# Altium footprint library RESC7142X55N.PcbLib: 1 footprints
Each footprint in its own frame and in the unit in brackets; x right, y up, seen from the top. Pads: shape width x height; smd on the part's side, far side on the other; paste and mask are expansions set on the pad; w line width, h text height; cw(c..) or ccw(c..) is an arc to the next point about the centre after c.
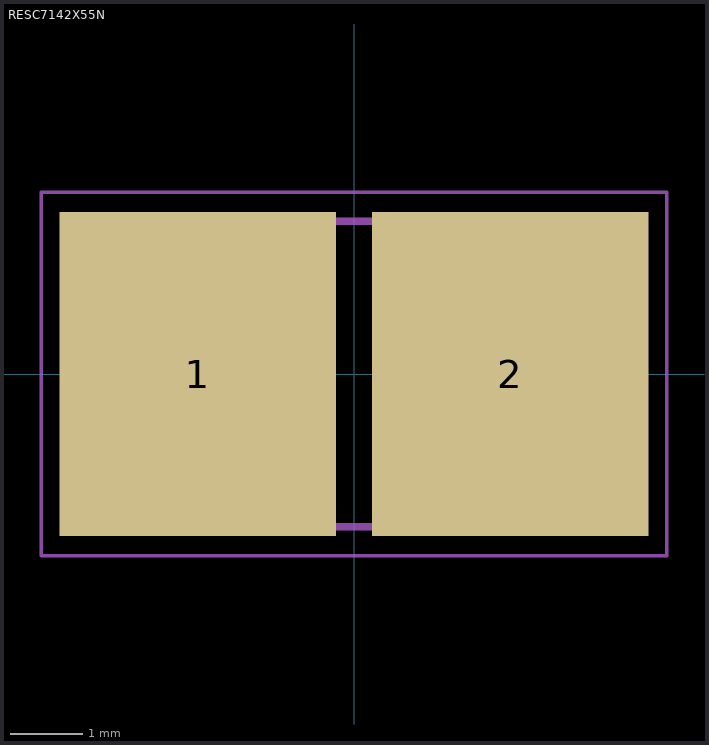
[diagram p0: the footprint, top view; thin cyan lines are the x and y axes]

## RESC7142X55N [mm]
pads (2):
  rect 3.8x4.45 smd: 1(-2.15,0) 2(2.15,0)
Mechanical 15:
  lines w0.1: -3.55,-2.1 3.55,-2.1 3.55,2.1 -3.55,2.1 -3.55,-2.1
Mechanical 20:
  lines w0.05: -4.3,-2.5 4.3,-2.5 4.3,2.5 -4.3,2.5 -4.3,-2.5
